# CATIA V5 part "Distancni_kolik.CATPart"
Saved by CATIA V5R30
Part number: Distancni_kolik
Definition: E 1300_6x36
Nomenclature: E 1300_6x36
Source: Unknown
Description: PART--DESC
Bounding box of the stored display mesh (mm): x 125.4 to 131.4, y -3 to 3, z 9.7 to 45.7
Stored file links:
  E:\Bakalarka\Model\Forma_v7\Distancni_kolik.CATPart
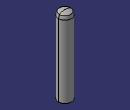
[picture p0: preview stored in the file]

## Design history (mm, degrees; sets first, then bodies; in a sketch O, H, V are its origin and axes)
Body1 "MANIFOLD_SOLID_BREP #3594" (main body)
  Solid1: solid without history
